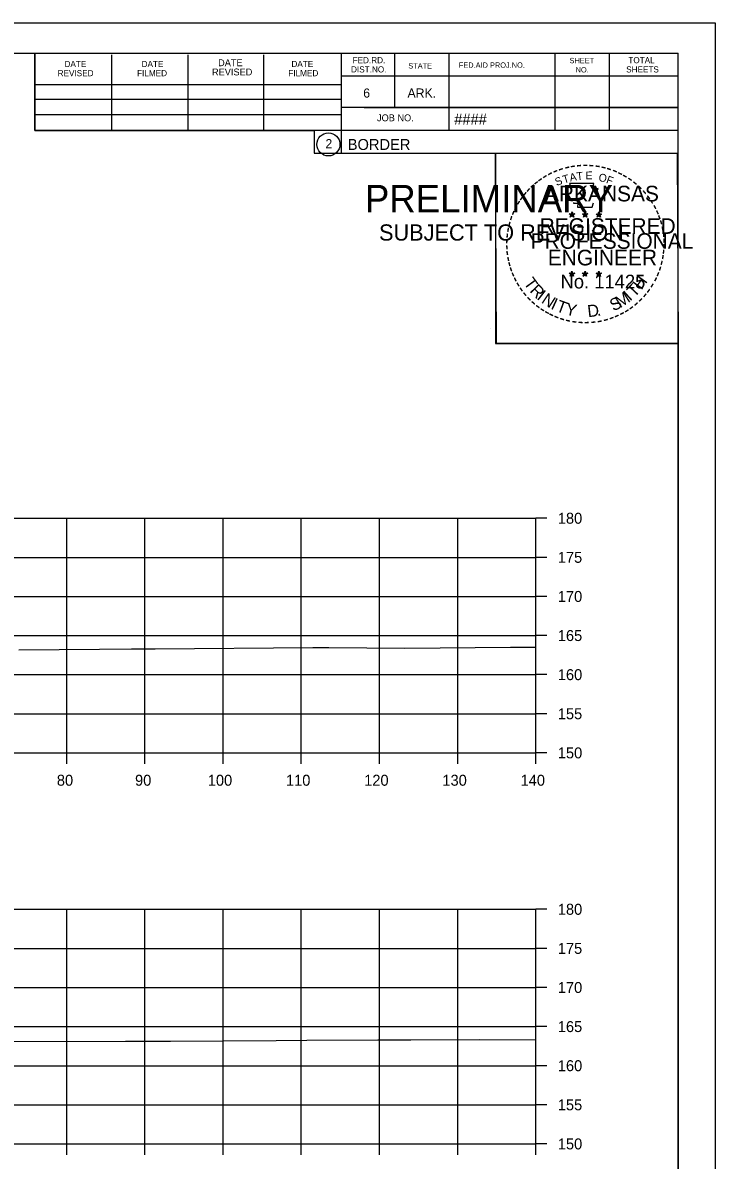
# Model space of a CAD drawing. Extents: x 1368503 to 1373085, y 379840 to 381833.
# Drawn here: x 1372996.5 to 1373085, y 380029.5 to 380175 of the extents above; entities that cross this region are included whole.
import ezdxf

# ---------------------------------------------------------------- set-up
doc = ezdxf.new("R2010")
doc.units = 0
for name, color, linetype in [('S_BRIDGE', 7, 'Continuous'), ('S_EDGE_PAVEMENT', 7, 'Continuous'), ('S_LANDSCAPING', 7, 'Continuous'), ('S_MISC_BOUNDARY', 7, 'Continuous'), ('S_MISC_BOUNDARY_ANNOT', 7, 'Continuous'), ('S_PHOTO_CENTERS', 7, 'Continuous'), ('S_PHOTO_NOTES', 7, 'Continuous'), ('S_TRAILS', 7, 'Continuous')]:
    doc.layers.add(name, color=color, linetype=linetype)

msp = doc.modelspace()

# ---------------------------------------------------------------- linework, layer by layer
at = {"layer": 'S_BRIDGE'}
for p, q in [((1372764.08, 380171.07), (1373080.26, 380171.07)), ((1372998, 380161.19), (1372998, 380171.07)), ((1373007.86, 380161.19), (1373007.86, 380170.87)), ((1373017.62, 380161.19), (1373017.62, 380170.87)), ((1373027.3, 380161.19), (1373027.3, 380170.87)), ((1373037.16, 380171.07), (1373037.16, 380158.27)), ((1373044, 380171.07), (1373044, 380164.13)), ((1373050.94, 380171.07), (1373050.94, 380161.19)), ((1373064.52, 380171.07), (1373064.52, 380161.19)), ((1373071.46, 380171.07), (1373071.46, 380161.19)), ((1373080.26, 379965.61), (1373080.26, 380171.07)), ((1373080.26, 380168.13), (1373037.16, 380168.13)), ((1373080.26, 380168.15), (1373080.26, 380168.15)), ((1372998, 380167.05), (1373037.16, 380167.05)), ((1372998, 380165.19), (1373037.16, 380165.19)), ((1373080.26, 380164.13), (1373037.16, 380164.13)), ((1373040.12, 380164.13), (1373080.26, 380164.13)), ((1372998, 380161.19), (1372998, 380163.25)), ((1372998, 380163.25), (1373037.16, 380163.25)), ((1373080.26, 380161.19), (1372998, 380161.19)), ((1373037.16, 380158.27), (1373080.26, 380158.27))]:
    msp.add_line(p, q, dxfattribs=at)
msp.add_circle((1373035.55, 380159.41), 1.47, dxfattribs=at)
at = {"layer": 'S_EDGE_PAVEMENT'}
for p, q in [((1373062.08, 380081.61), (1373062.08, 380111.61)), ((1373063.48, 380111.61), (1373062.08, 380111.61)), ((1373063.48, 380106.61), (1373062.08, 380106.61)), ((1373063.48, 380101.61), (1373062.08, 380101.61)), ((1373063.48, 380096.61), (1373062.08, 380096.61)), ((1373063.48, 380091.61), (1373062.08, 380091.61)), ((1373063.48, 380086.61), (1373062.08, 380086.61)), ((1372782.08, 380081.61), (1373062.08, 380081.61)), ((1373002.08, 380080.21), (1373002.08, 380081.61)), ((1373012.08, 380080.21), (1373012.08, 380081.61)), ((1373022.08, 380080.21), (1373022.08, 380081.61)), ((1373032.08, 380080.21), (1373032.08, 380081.61)), ((1373042.08, 380080.21), (1373042.08, 380081.61)), ((1373052.08, 380080.21), (1373052.08, 380081.61)), ((1373062.08, 380080.21), (1373062.08, 380081.61)), ((1373063.48, 380081.61), (1373062.08, 380081.61)), ((1373062.08, 380031.61), (1373062.08, 380061.61)), ((1373063.48, 380061.61), (1373062.08, 380061.61)), ((1373063.48, 380056.61), (1373062.08, 380056.61)), ((1373063.48, 380051.61), (1373062.08, 380051.61)), ((1373063.48, 380046.61), (1373062.08, 380046.61)), ((1373063.48, 380041.61), (1373062.08, 380041.61)), ((1373063.48, 380036.61), (1373062.08, 380036.61)), ((1372782.08, 380031.61), (1373062.08, 380031.61)), ((1373002.08, 380030.21), (1373002.08, 380031.61)), ((1373012.08, 380030.21), (1373012.08, 380031.61)), ((1373022.08, 380030.21), (1373022.08, 380031.61)), ((1373032.08, 380030.21), (1373032.08, 380031.61)), ((1373042.08, 380030.21), (1373042.08, 380031.61)), ((1373052.08, 380030.21), (1373052.08, 380031.61)), ((1373062.08, 380030.21), (1373062.08, 380031.61)), ((1373063.48, 380031.61), (1373062.08, 380031.61))]:
    msp.add_line(p, q, dxfattribs=at)
at = {"layer": 'S_LANDSCAPING'}
for p, q in [((1373066.35, 380150.53), (1373066.7, 380150.42)), ((1373066.35, 380150.53), (1373066.6, 380150.48)), ((1373066.35, 380150.53), (1373066.58, 380150.4)), ((1373066.7, 380150.78), (1373066.65, 380150.53)), ((1373066.7, 380150.42), (1373066.7, 380150.78)), ((1373066.7, 380150.78), (1373066.74, 380150.53)), ((1373067.04, 380150.53), (1373066.7, 380150.42)), ((1373067.04, 380150.53), (1373066.76, 380150.48)), ((1373067.04, 380150.53), (1373066.84, 380150.42)), ((1373068.02, 380150.53), (1373068.37, 380150.42)), ((1373068.02, 380150.53), (1373068.27, 380150.48)), ((1373068.02, 380150.53), (1373068.25, 380150.4)), ((1373068.37, 380150.78), (1373068.32, 380150.53)), ((1373068.37, 380150.42), (1373068.37, 380150.78)), ((1373068.37, 380150.78), (1373068.41, 380150.53)), ((1373068.71, 380150.53), (1373068.37, 380150.42)), ((1373068.71, 380150.53), (1373068.43, 380150.48)), ((1373068.71, 380150.53), (1373068.51, 380150.42)), ((1373069.78, 380150.51), (1373070.13, 380150.4)), ((1373069.78, 380150.51), (1373070.03, 380150.47)), ((1373069.78, 380150.51), (1373070.02, 380150.39)), ((1373070.13, 380150.77), (1373070.09, 380150.52)), ((1373070.13, 380150.4), (1373070.13, 380150.77)), ((1373070.13, 380150.77), (1373070.18, 380150.52)), ((1373070.48, 380150.51), (1373070.13, 380150.4)), ((1373070.48, 380150.51), (1373070.19, 380150.47)), ((1373070.48, 380150.51), (1373070.27, 380150.41)), ((1373066.48, 380150.12), (1373066.7, 380150.42)), ((1373066.48, 380150.12), (1373066.61, 380150.36)), ((1373066.48, 380150.12), (1373066.69, 380150.34)), ((1373066.91, 380150.12), (1373066.69, 380150.33)), ((1373066.91, 380150.12), (1373066.7, 380150.42)), ((1373066.91, 380150.12), (1373066.77, 380150.41)), ((1373068.15, 380150.12), (1373068.37, 380150.42)), ((1373068.15, 380150.12), (1373068.28, 380150.36)), ((1373068.15, 380150.12), (1373068.36, 380150.34)), ((1373068.58, 380150.12), (1373068.36, 380150.33)), ((1373068.58, 380150.12), (1373068.37, 380150.42)), ((1373068.58, 380150.12), (1373068.44, 380150.41)), ((1373069.91, 380150.11), (1373070.13, 380150.4)), ((1373069.91, 380150.11), (1373070.04, 380150.35)), ((1373069.91, 380150.11), (1373070.13, 380150.32)), ((1373070.34, 380150.11), (1373070.13, 380150.4)), ((1373070.34, 380150.11), (1373070.13, 380150.32)), ((1373070.34, 380150.11), (1373070.21, 380150.4)), ((1373066.34, 380142.95), (1373066.69, 380142.84)), ((1373066.34, 380142.95), (1373066.6, 380142.91)), ((1373066.34, 380142.95), (1373066.58, 380142.83)), ((1373066.48, 380142.55), (1373066.69, 380142.84)), ((1373066.48, 380142.55), (1373066.6, 380142.79)), ((1373066.48, 380142.55), (1373066.69, 380142.76)), ((1373066.69, 380143.21), (1373066.65, 380142.96)), ((1373066.69, 380142.84), (1373066.69, 380143.21)), ((1373066.69, 380143.21), (1373066.74, 380142.96)), ((1373067.04, 380142.95), (1373066.69, 380142.84)), ((1373066.9, 380142.55), (1373066.69, 380142.84)), ((1373066.9, 380142.55), (1373066.69, 380142.76)), ((1373067.04, 380142.95), (1373066.75, 380142.9)), ((1373066.9, 380142.55), (1373066.77, 380142.84)), ((1373067.04, 380142.95), (1373066.83, 380142.85)), ((1373068.01, 380142.95), (1373068.36, 380142.84)), ((1373068.01, 380142.95), (1373068.26, 380142.91)), ((1373068.01, 380142.95), (1373068.25, 380142.83)), ((1373068.14, 380142.55), (1373068.36, 380142.84)), ((1373068.14, 380142.55), (1373068.27, 380142.79)), ((1373068.14, 380142.55), (1373068.36, 380142.76)), ((1373068.36, 380143.21), (1373068.32, 380142.96)), ((1373068.36, 380142.84), (1373068.36, 380143.21)), ((1373068.36, 380143.21), (1373068.41, 380142.96)), ((1373068.71, 380142.95), (1373068.36, 380142.84)), ((1373068.57, 380142.55), (1373068.36, 380142.84)), ((1373068.57, 380142.55), (1373068.36, 380142.76)), ((1373068.71, 380142.95), (1373068.42, 380142.9)), ((1373068.57, 380142.55), (1373068.44, 380142.84)), ((1373068.71, 380142.95), (1373068.5, 380142.85)), ((1373069.78, 380142.94), (1373070.13, 380142.83)), ((1373069.78, 380142.94), (1373070.03, 380142.9)), ((1373069.78, 380142.94), (1373070.02, 380142.82)), ((1373069.91, 380142.54), (1373070.13, 380142.83)), ((1373069.91, 380142.54), (1373070.04, 380142.78)), ((1373069.91, 380142.54), (1373070.13, 380142.75)), ((1373070.13, 380143.2), (1373070.09, 380142.95)), ((1373070.13, 380142.83), (1373070.13, 380143.2)), ((1373070.13, 380143.2), (1373070.18, 380142.95)), ((1373070.47, 380142.94), (1373070.13, 380142.83)), ((1373070.34, 380142.54), (1373070.13, 380142.83)), ((1373070.34, 380142.54), (1373070.13, 380142.75)), ((1373070.47, 380142.94), (1373070.19, 380142.89)), ((1373070.34, 380142.54), (1373070.2, 380142.83)), ((1373070.47, 380142.94), (1373070.27, 380142.84))]:
    msp.add_line(p, q, dxfattribs=at)
for points in [[(1373066.39, 380154.4), (1373066.66, 380153.58)], [(1373069.9, 380153.48), (1373070.04, 380153.77), (1373069.36, 380153.74), (1373069.5, 380154.4), (1373066.39, 380154.4)], [(1373066.88, 380151.98), (1373066.88, 380151.89), (1373067.44, 380151.88), (1373067.39, 380151.4), (1373069.26, 380151.4), (1373069.46, 380151.94)], [(1373066.7, 380150.78), (1373066.91, 380150.12), (1373066.35, 380150.53), (1373067.04, 380150.53), (1373066.48, 380150.12), (1373066.7, 380150.78)], [(1373068.37, 380150.78), (1373068.58, 380150.12), (1373068.02, 380150.53), (1373068.71, 380150.53), (1373068.15, 380150.12), (1373068.37, 380150.78)], [(1373070.13, 380150.77), (1373070.34, 380150.11), (1373069.78, 380150.51), (1373070.48, 380150.51), (1373069.91, 380150.11), (1373070.13, 380150.77)], [(1373066.69, 380143.21), (1373066.9, 380142.55), (1373066.34, 380142.95), (1373067.04, 380142.95), (1373066.48, 380142.55), (1373066.69, 380143.21)], [(1373068.36, 380143.21), (1373068.57, 380142.55), (1373068.01, 380142.95), (1373068.71, 380142.95), (1373068.14, 380142.55), (1373068.36, 380143.21)], [(1373070.13, 380143.2), (1373070.34, 380142.54), (1373069.78, 380142.94), (1373070.47, 380142.94), (1373069.91, 380142.54), (1373070.13, 380143.2)]]:
    msp.add_lwpolyline(points, dxfattribs=at)
for centre, radius in [((1373066.69, 380150.41), 0.172), ((1373066.69, 380150.41), 0.145), ((1373066.69, 380150.41), 0.116), ((1373066.69, 380150.41), 0.0991), ((1373066.69, 380150.41), 0.0747), ((1373068.36, 380150.41), 0.172), ((1373068.36, 380150.41), 0.145), ((1373068.36, 380150.41), 0.116), ((1373068.36, 380150.41), 0.0991), ((1373068.36, 380150.41), 0.0747), ((1373070.13, 380150.4), 0.172), ((1373070.13, 380150.4), 0.145), ((1373070.13, 380150.4), 0.116), ((1373070.13, 380150.4), 0.0991), ((1373066.69, 380150.41), 0.0495), ((1373066.69, 380150.41), 0.0296), ((1373068.36, 380150.41), 0.0495), ((1373068.36, 380150.41), 0.0296), ((1373070.13, 380150.4), 0.0747), ((1373070.13, 380150.4), 0.0495), ((1373070.13, 380150.4), 0.0296), ((1373066.69, 380142.84), 0.172), ((1373066.69, 380142.84), 0.145), ((1373066.69, 380142.84), 0.116), ((1373066.69, 380142.84), 0.0991), ((1373066.69, 380142.84), 0.0747), ((1373066.69, 380142.84), 0.0495), ((1373066.69, 380142.84), 0.0296), ((1373068.36, 380142.84), 0.172), ((1373068.36, 380142.84), 0.145), ((1373068.36, 380142.84), 0.116), ((1373068.36, 380142.84), 0.0991), ((1373068.36, 380142.84), 0.0747), ((1373068.36, 380142.84), 0.0495), ((1373068.36, 380142.84), 0.0296), ((1373070.13, 380142.83), 0.172), ((1373070.13, 380142.83), 0.145), ((1373070.13, 380142.83), 0.116), ((1373070.13, 380142.83), 0.0991), ((1373070.13, 380142.83), 0.0747), ((1373070.13, 380142.83), 0.0495), ((1373070.13, 380142.83), 0.0296)]:
    msp.add_circle(centre, radius, dxfattribs=at)
at = {"layer": 'S_MISC_BOUNDARY'}
for points in [[(1372995.94, 380094.78), (1373006.29, 380094.88), (1373010.37, 380094.9), (1373013.39, 380094.92), (1373033.55, 380095.09), (1373034.86, 380095.1), (1373035.58, 380095.1), (1373045.33, 380094.99), (1373058.83, 380095.12), (1373062.08, 380095.12)], [(1372994.3, 380044.7), (1373009.62, 380044.74), (1373015.34, 380044.76), (1373028.88, 380044.85), (1373032.77, 380044.86), (1373041.87, 380044.9), (1373046.07, 380044.92), (1373054.88, 380044.95), (1373062.08, 380044.91)]]:
    msp.add_lwpolyline(points, dxfattribs=at)
at = {"layer": 'S_PHOTO_CENTERS'}
for p, q in [((1372782.08, 380111.61), (1373062.08, 380111.61)), ((1373002.08, 380081.61), (1373002.08, 380111.61)), ((1373012.08, 380081.61), (1373012.08, 380111.61)), ((1373022.08, 380081.61), (1373022.08, 380111.61)), ((1373032.08, 380081.61), (1373032.08, 380111.61)), ((1373042.08, 380081.61), (1373042.08, 380111.61)), ((1373052.08, 380081.61), (1373052.08, 380111.61)), ((1373062.08, 380081.61), (1373062.08, 380111.61)), ((1372782.08, 380106.61), (1373062.08, 380106.61)), ((1372782.08, 380101.61), (1373062.08, 380101.61)), ((1372782.08, 380096.61), (1373062.08, 380096.61)), ((1372782.08, 380091.61), (1373062.08, 380091.61)), ((1372782.08, 380086.61), (1373062.08, 380086.61)), ((1372782.08, 380081.61), (1373062.08, 380081.61)), ((1372782.08, 380061.61), (1373062.08, 380061.61)), ((1373002.08, 380031.61), (1373002.08, 380061.61)), ((1373012.08, 380031.61), (1373012.08, 380061.61)), ((1373022.08, 380031.61), (1373022.08, 380061.61)), ((1373032.08, 380031.61), (1373032.08, 380061.61)), ((1373042.08, 380031.61), (1373042.08, 380061.61)), ((1373052.08, 380031.61), (1373052.08, 380061.61)), ((1373062.08, 380031.61), (1373062.08, 380061.61)), ((1372782.08, 380056.61), (1373062.08, 380056.61)), ((1372782.08, 380051.61), (1373062.08, 380051.61)), ((1372782.08, 380046.61), (1373062.08, 380046.61)), ((1372782.08, 380041.61), (1373062.08, 380041.61)), ((1372782.08, 380036.61), (1373062.08, 380036.61)), ((1372782.08, 380031.61), (1373062.08, 380031.61))]:
    msp.add_line(p, q, dxfattribs=at)
at = {"layer": 'S_PHOTO_NOTES'}
for p, q in [((1372751.68, 380174.97), (1373085.01, 380174.97)), ((1373056.3, 380135.82), (1373056.3, 380135.82))]:
    msp.add_line(p, q, dxfattribs=at)
for points in [[(1372751.67, 380174.97), (1373085.01, 380174.97), (1373085.01, 379961.63), (1372751.67, 379961.63)], [(1372998, 380171.07), (1372998, 380161.19), (1373033.73, 380161.19), (1373033.73, 380158.27), (1373056.93, 380158.27), (1373056.93, 380133.94), (1373080.26, 380133.94), (1373080.26, 379965.61), (1372764.08, 379965.61), (1372764.08, 380171.07)], [(1373056.93, 380158.27), (1373080.14, 380158.27), (1373080.26, 380133.94), (1373057.05, 380133.94)]]:
    msp.add_lwpolyline(points, close=True, dxfattribs=at)

# ---------------------------------------------------------------- texts
at = {"layer": 'S_BRIDGE'}
for s, height, p in [('DATE', 0.782, (1373001.8, 380169.31)), ('DATE', 0.782, (1373011.66, 380169.31)), ('DATE', 0.879, (1373021.44, 380169.41)), ('DATE', 0.782, (1373030.82, 380169.31)), ('DIST.NO.', 0.782, (1373038.44, 380168.61)), ('FED.RD.', 0.782, (1373038.64, 380169.79)), ('STATE', 0.684, (1373045.76, 380169.11)), ('FED.AID PROJ.NO.', 0.684, (1373052.22, 380169.21)), ('SHEET', 0.684, (1373066.38, 380169.79)), ('SHEETS', 0.782, (1373073.62, 380168.61)), ('TOTAL', 0.782, (1373073.9, 380169.79)), ('REVISED', 0.782, (1373000.92, 380168.13)), ('FILMED', 0.782, (1373011.08, 380168.13)), ('REVISED', 0.879, (1373020.66, 380168.23)), ('FILMED', 0.782, (1373030.42, 380168.13)), ('NO.', 0.684, (1373067.16, 380168.61)), ('6', 1.17, (1373040, 380165.39)), ('ARK.', 1.172, (1373045.66, 380165.39)), ('JOB NO.', 0.879, (1373041.76, 380162.37)), ('####', 1.4, (1373051.64, 380161.93)), ('2', 1.17, (1373035.17, 380158.92)), ('BORDER', 1.4, (1373038.02, 380158.7))]:
    msp.add_text(s, height=height, rotation=360, dxfattribs=at).set_placement(p)
at = {"layer": 'S_LANDSCAPING'}
for s, height, rotation, p in [('-', 1.6, 19.1761, (1373065.14, 380155.53)), ('-', 1.6, 13.6301, (1373065.89, 380155.77)), ('-', 1.6, 10.2193, (1373066.56, 380155.93)), ('-', 1.6, 5.8968, (1373067.29, 380156.04)), ('-', 1.6, 0.1862, (1373068.06, 380156.12)), ('-', 1.6, 357.743, (1373068.79, 380156.1)), ('-', 1.6, 352.1617, (1373069.53, 380156.05)), ('-', 1.6, 347.2049, (1373070.25, 380155.93)), ('-', 1.6, 342.3362, (1373070.89, 380155.78)), ('-', 1.6, 36.2317, (1373062.69, 380154.18)), ('-', 1.6, 34.0636, (1373063.27, 380154.58)), ('-', 1.6, 28.7918, (1373063.87, 380154.95)), ('-', 1.6, 24.3072, (1373064.5, 380155.26)), ('S', 1, 21.594, (1373064.74, 380154.08)), ('T', 1, 16.4036, (1373065.66, 380154.41)), ('A', 1, 11.2132, (1373066.48, 380154.66)), ('T', 1, 6.0228, (1373067.33, 380154.83)), ('E', 1, 0.8323, (1373068.44, 380154.94)), ('O', 1, 350.4515, (1373070.04, 380154.73)), ('F', 1, 340.0707, (1373070.99, 380154.5)), ('-', 1.6, 337.8551, (1373071.62, 380155.56)), ('-', 1.6, 334.1211, (1373072.25, 380155.28)), ('-', 1.6, 329.6409, (1373072.83, 380155)), ('-', 1.6, 325.8627, (1373073.47, 380154.64)), ('-', 1.6, 48.423, (1373061.34, 380152.91)), ('-', 1.6, 42.9622, (1373061.78, 380153.39)), ('-', 1.6, 38.9507, (1373062.22, 380153.8)), ('ARKANSAS', 2, 360, (1373063.24, 380152.12)), ('-', 1.6, 320.5297, (1373074.08, 380154.21)), ('-', 1.6, 315.5786, (1373074.68, 380153.73)), ('-', 1.6, 309.8797, (1373075.25, 380153.18)), ('-', 1.6, 58.0706, (1373060.2, 380151.33)), ('-', 1.6, 54.2325, (1373060.52, 380151.85)), ('-', 1.6, 50.6142, (1373060.93, 380152.42)), ('-', 1.6, 306.6522, (1373075.78, 380152.57)), ('-', 1.4, 303.6753, (1373076.26, 380152.01)), ('-', 1.6, 67.7743, (1373059.62, 380150.1)), ('-', 1.6, 62.8713, (1373059.88, 380150.71)), ('-', 1.6, 299.6684, (1373076.58, 380151.4)), ('-', 1.6, 294.6628, (1373076.91, 380150.79)), ('-', 1.6, 75.461, (1373059.21, 380148.76)), ('-', 1.6, 72.3945, (1373059.4, 380149.47)), ('REGISTERED', 2, 360, (1373062.56, 380147.97)), ('DWB', 0.01, 360, (1373066.68, 380150.41)), ('DWB', 0.01, 360, (1373068.35, 380150.41)), ('DWB', 0.01, 360, (1373070.12, 380150.4)), ('-', 1.6, 290.5728, (1373077.16, 380150.21)), ('-', 1.6, 285.1233, (1373077.4, 380149.63)), ('-', 1.6, 85.1863, (1373059, 380147.35)), ('-', 1.6, 81.2013, (1373059.08, 380148.05)), ('PROFESSIONAL', 2, 360, (1373061.41, 380146.06)), ('-', 1.6, 280.5493, (1373077.6, 380148.89)), ('-', 1.6, 276.5962, (1373077.76, 380148.12)), ('-', 1.6, 94.1959, (1373059.01, 380145.93)), ('-', 1.6, 89.0622, (1373058.97, 380146.65)), ('-', 1.6, 274.3301, (1373077.82, 380147.4)), ('-', 1.6, 269.9407, (1373077.85, 380146.77)), ('-', 1.6, 98.9479, (1373059.08, 380145.26)), ('-', 1.6, 101.7149, (1373059.22, 380144.53)), ('ENGINEER', 2, 360, (1373063.6, 380143.94)), ('-', 1.6, 260.9953, (1373077.76, 380145.45)), ('-', 1.6, 263.5172, (1373077.83, 380146.1)), ('-', 1.6, 105.4578, (1373059.38, 380143.93)), ('-', 1.6, 109.0874, (1373059.59, 380143.3)), ('-', 1.6, 252.8681, (1373077.47, 380144.05)), ('-', 1.6, 255.7626, (1373077.65, 380144.77)), ('-', 1.6, 114.0643, (1373059.85, 380142.71)), ('-', 1.6, 115.7289, (1373060.15, 380142.09)), ('-', 1.6, 120.4471, (1373060.51, 380141.5)), ('T', 1.54, 306.0406, (1373060.45, 380141.68)), ('No. 11425', 1.757, 360, (1373065.23, 380140.99)), ('DWB', 0.01, 360, (1373066.68, 380142.84)), ('DWB', 0.01, 360, (1373068.35, 380142.84)), ('DWB', 0.01, 360, (1373070.11, 380142.83)), ('H', 1.54, 54.6088, (1373075.57, 380140.72)), ('-', 1.6, 244.6197, (1373076.99, 380142.75)), ('-', 1.6, 247.8887, (1373077.25, 380143.38)), ('-', 1.6, 125.8934, (1373060.91, 380140.94)), ('-', 1.6, 130.7181, (1373061.37, 380140.39)), ('R', 1.54, 314.005, (1373061.21, 380140.63)), ('I', 1.54, 321.9694, (1373062.11, 380139.7)), ('N', 1.54, 326.5002, (1373062.68, 380139.23)), ('M', 1.54, 32.6563, (1373072.84, 380138.45)), ('I', 1.54, 42.1136, (1373074.12, 380139.3)), ('T', 1.54, 46.6444, (1373074.68, 380139.77)), ('-', 1.6, 231.2538, (1373075.76, 380140.78)), ('-', 1.6, 233.8452, (1373076.19, 380141.34)), ('-', 1.6, 239.0712, (1373076.59, 380141.99)), ('-', 1.6, 134.2238, (1373061.89, 380139.84)), ('-', 1.6, 138.9338, (1373062.42, 380139.38)), ('-', 1.6, 144.6463, (1373062.97, 380138.97)), ('I', 1.54, 335.3603, (1373063.89, 380138.44)), ('T', 1.54, 339.8912, (1373064.55, 380138.12)), ('Y', 1.54, 347.8556, (1373065.77, 380137.67)), ('D', 1.54, 6.3969, (1373068.75, 380137.31)), ('S', 1.54, 26.9312, (1373072, 380138.04)), ('-', 1.6, 221.0851, (1373074.76, 380139.7)), ('-', 1.6, 225.7653, (1373075.28, 380140.21)), ('-', 1.6, 148.0898, (1373063.53, 380138.6)), ('-', 1.6, 151.5704, (1373064.11, 380138.28)), ('-', 1.6, 154.6002, (1373064.63, 380138.03)), ('-', 1.6, 158.5612, (1373065.26, 380137.78)), ('.', 1.54, 13.7642, (1373069.94, 380137.44)), ('-', 1.6, 204.2516, (1373072.49, 380138.18)), ('-', 1.6, 207.3568, (1373073.12, 380138.5)), ('-', 1.6, 212.2491, (1373073.68, 380138.84)), ('-', 1.6, 215.7363, (1373074.21, 380139.23)), ('-', 1.6, 162.7983, (1373065.95, 380137.56)), ('-', 1.6, 167.5555, (1373066.66, 380137.4)), ('-', 1.6, 173.1155, (1373067.43, 380137.29)), ('-', 1.6, 176.5183, (1373068.18, 380137.24)), ('-', 1.6, 181.5918, (1373068.92, 380137.26)), ('-', 1.6, 185.8167, (1373069.73, 380137.33)), ('-', 1.6, 191.2858, (1373070.47, 380137.46)), ('-', 1.6, 195.4743, (1373071.2, 380137.66)), ('-', 1.6, 200.7184, (1373071.88, 380137.91))]:
    msp.add_text(s, height=height, rotation=rotation, dxfattribs=at).set_placement(p)
at = {"layer": 'S_MISC_BOUNDARY_ANNOT'}
for s, height, p in [('PRELIMINARY', 3.5, (1373040.21, 380150.73)), ('DWB', 0.01, (1373040.96, 380152.58)), ('SUBJECT TO REVISION', 2.0751, (1373042.02, 380147.11))]:
    msp.add_text(s, height=height, rotation=360, dxfattribs=at).set_placement(p)
at = {"layer": 'S_TRAILS'}
for s, p in [('180', (1373064.88, 380110.91)), ('175', (1373064.88, 380105.91)), ('170', (1373064.88, 380100.91)), ('165', (1373064.88, 380095.91)), ('160', (1373064.88, 380090.91)), ('155', (1373064.88, 380085.91)), ('150', (1373064.88, 380080.91)), ('80', (1373000.82, 380077.41)), ('90', (1373010.82, 380077.41)), ('100', (1373020.12, 380077.41)), ('110', (1373030.12, 380077.41)), ('120', (1373040.12, 380077.41)), ('130', (1373050.12, 380077.41)), ('140', (1373060.12, 380077.41)), ('180', (1373064.88, 380060.91)), ('175', (1373064.88, 380055.91)), ('170', (1373064.88, 380050.91)), ('165', (1373064.88, 380045.91)), ('160', (1373064.88, 380040.91)), ('155', (1373064.88, 380035.91)), ('150', (1373064.88, 380030.91))]:
    msp.add_text(s, height=1.4, dxfattribs=at).set_placement(p)

doc.saveas('drawing.dxf')
